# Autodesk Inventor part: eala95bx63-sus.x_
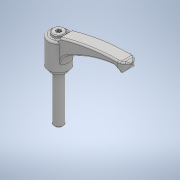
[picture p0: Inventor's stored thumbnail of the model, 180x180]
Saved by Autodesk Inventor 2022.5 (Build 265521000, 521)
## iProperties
Created: 2018-05
Part Number: eala95bx63-sus.x_
Material: 一般
Document SubType Name: Modeling
Designer: imaocorp
Density: 1 g/cm^3
Appearance: 既定
Sending System: SOLIDWORKS 2016-2016286
MC: AMD64
MC_MODEL: AMD64 Family 21 Model 2 Stepping 0, AuthenticAMD
OS: Windows_NT
FRU: Parasolid Version 28.0, build 224,  7-29-2016
FORMAT: text
GUISE: transmit
KEY: eala95bx63-sus
FILE: eala95bx63-sus.x_t
DATE: Fri May 18 11:34:08 2018
Author: imaocorp
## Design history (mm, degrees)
feature "Base1"
node "ソリッド1"
